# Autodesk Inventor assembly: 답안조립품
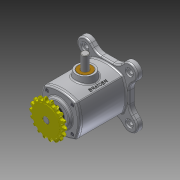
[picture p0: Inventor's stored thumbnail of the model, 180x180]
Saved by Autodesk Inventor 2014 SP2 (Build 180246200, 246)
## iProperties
Created: 2016-05
Part Number: 답안조립품
Document SubType Name: Assembly
Designer: 달님반
Author: 달님반
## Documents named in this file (11)
- C:\Users\달님반\Desktop\460507v1028\답안조립품.iam
- C:\Users\달님반\Desktop\460507v1028\본체.ipt
- C:\Users\달님반\Desktop\460507v1028\M4x0.7x12.ipt
- C:\Users\달님반\Desktop\460507v1028\베어링-6203.ipt
- C:\Users\달님반\Desktop\460507v1028\부시.ipt
- C:\Users\달님반\Desktop\460507v1028\스프로킷.ipt
- C:\Users\달님반\Desktop\460507v1028\슬라이더.ipt
- C:\Users\달님반\Desktop\460507v1028\오일실.ipt
- C:\Users\달님반\Desktop\460507v1028\커버.ipt
- C:\Users\달님반\Desktop\460507v1028\키5x5.ipt
- C:\Users\달님반\Desktop\460507v1028\편심축.ipt
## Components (8 placed, 1 different names)
1. M4x0.7x12:1
2. M4x0.7x12:2
3. M4x0.7x12:3
4. M4x0.7x12:4
5. M4x0.7x12:5
6. M4x0.7x12:6
7. M4x0.7x12:7
8. M4x0.7x12:8
## Named parameters: d14_d1 = 0, d15_d2 = 0, d16_d3 = 0, d17_d4 = 0
